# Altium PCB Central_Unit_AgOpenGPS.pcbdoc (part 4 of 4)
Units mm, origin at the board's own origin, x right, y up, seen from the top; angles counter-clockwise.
Board outline 200.19 x 122.57 mm, 2 copper layers (Top Layer, Bottom Layer); 271 components, 213 nets, 1023 pads, 412 vias.
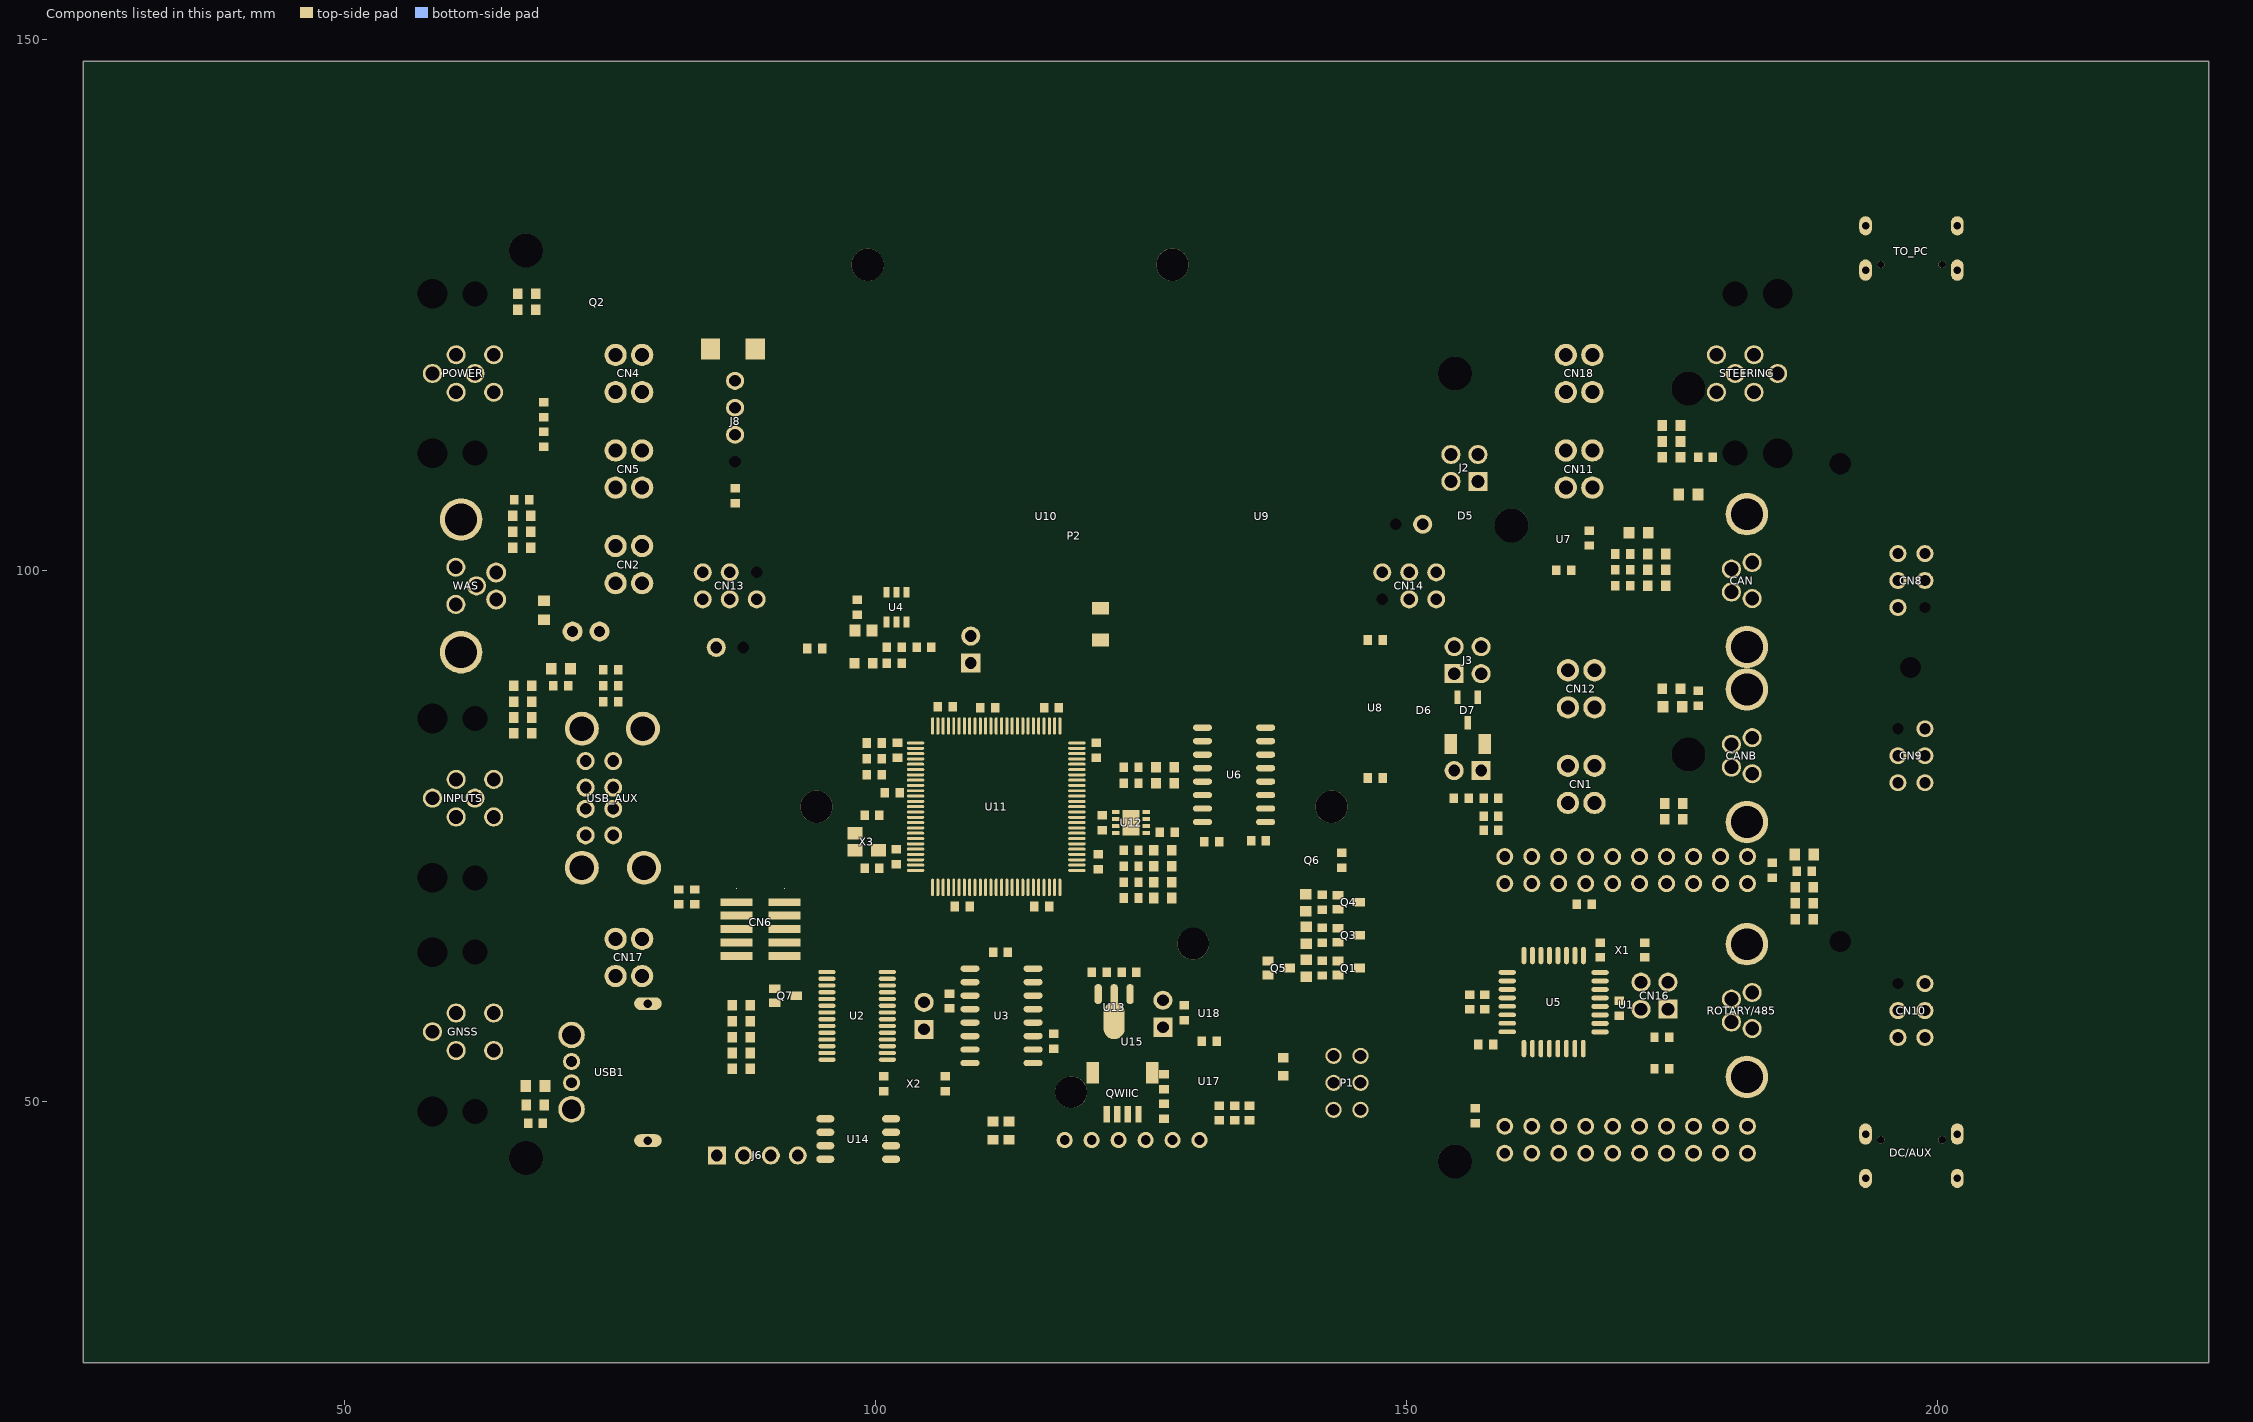
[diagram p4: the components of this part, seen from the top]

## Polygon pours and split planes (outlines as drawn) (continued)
GND2 on Top Layer (solid): 192.987,42.366 202.387,42.366 202.487,42.466 202.487,87.766 201.087,89.166 194.187,89.166 192.887,87.866
+3V3 on Top Layer (solid): 104.187,75.366 104.187,83.866 105.387,85.066 105.287,85.066 105.387,85.066 117.387,85.066 118.687,83.766 118.687,71.766 117.387,70.466 107.987,70.666 105.137,73.516 104.487,73.666 104.187,74.866
GND on Top Layer (solid): 53.888,132.116 54.838,133.066 56.088,133.066 108.638,133.066 118.837,133.066 143.887,133.066 169.037,133.066 179.687,133.066 189.137,133.066 189.137,42.616 188.587,42.066 54.688,42.066 53.788,42.966

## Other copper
Top Layer:
  region: 191.387,65.566 191.387,64.566 190.387,64.566 190.387,65.566
  region: 196.987,91.366 197.987,91.366 197.987,90.366 196.987,90.366
  region: 191.387,110.566 191.387,109.566 190.387,109.566 190.387,110.566
  rectangle net MB: 167.787,120.066 178.787,122.416
  rectangle net +5V: 115.837,44.416 116.437,44.666
  rectangle net +MOTOR: 99.587,122.116 102.787,125.816
  rectangle net MA: 105.087,116.966 126.237,130.816
  rectangle net STEERENABLE: 136.487,63.566 136.987,64.266
  rectangle net +3V3: 130.637,58.166 131.687,58.566
  rectangle net +5V: 94.987,89.966 98.487,91.166
  rectangle net +5V: 95.287,90.766 97.487,91.566
  rectangle net +5V: 95.587,91.566 96.087,92.566
  rectangle net +5V: 94.687,90.866 95.787,93.766
  rectangle net +VIN: 96.087,96.866 98.187,98.066
  rectangle net +3V3: 135.187,57.566 135.887,58.666
  rectangle net MB: 135.928,101.063 136.822,106.039
  rectangle net VBUS1: 199.687,125.966 200.287,127.166
  rectangle net VBUS1: 194.887,125.966 195.487,127.166
  rectangle net DP2: 197.187,48.166 197.387,48.966
  rectangle net VBUS2: 199.687,47.166 200.287,48.966
  rectangle net VBUS2: 194.887,46.966 195.487,48.766
  rectangle net MB: 130.887,105.766 152.387,122.366
  rectangle net GND: 98.987,95.866 104.287,97.266
  rectangle net +VIN: 97.787,97.466 101.287,98.166
  rectangle net +VIN: 96.487,97.966 101.287,99.666
  rectangle net +SMPS: 96.087,100.266 98.087,103.666
  rectangle net -MOTOR: 86.787,123.866 90.587,126.266
  rectangle net +MOTOR: 119.487,97.366 126.087,101.466
  rectangle net -MOTOR: 126.787,95.866 132.687,101.516
  rectangle net MB: 130.887,121.966 179.537,130.966
  rectangle net MA: 110.887,105.566 130.687,126.866
  rectangle net -MOTOR: 126.787,100.766 132.987,105.266
  rectangle net -MOTOR: 111.787,102.166 127.087,105.266
  rectangle net -MOTOR: 111.887,101.366 112.687,102.366
  rectangle net GND: 120.887,55.466 124.137,58.916
  rectangle net GND: 121.587,58.616 123.387,63.266
  region net +MOTOR: 140.197,99.782 140.703,99.782 142.087,101.166 143.187,102.266 143.187,103.966 140.287,103.966 139.787,103.466 139.787,100.192 140.197,99.782
Bottom Layer:
  region: 191.387,65.566 191.387,64.566 190.387,64.566 190.387,65.566
  region: 196.987,91.366 197.987,91.366 197.987,90.366 196.987,90.366
  region: 191.387,110.566 191.387,109.566 190.387,109.566 190.387,110.566
  rectangle net -MOTOR: 65.387,114.666 74.087,118.766
  rectangle net -MOTOR: 63.487,118.266 75.987,121.666
  rectangle net VBUS1: 195.487,103.766 199.387,106.266
  rectangle net VBUS2: 195.587,51.066 199.487,53.566
  rectangle net MA: 186.087,117.816 189.188,122.006
  rectangle net +MOTOR: 53.587,113.416 62.237,117.416

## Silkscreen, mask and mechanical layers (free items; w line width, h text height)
Top Overlay:
  lines w0.15 net S$18375: 53.287,43.563 189.287,43.566 ; 53.287,131.566 189.387,131.566
  lines w0.15 net S$55412: 94.587,128.666 96.987,131.066 97.687,131.066 129.887,131.066 132.387,128.566 143.787,128.566 145.287,127.066
  lines w0.15 net S$55414: 91.887,126.966 91.887,127.666 92.887,128.666 94.587,128.666
  lines w0.15 net S$55416: 145.287,120.166 145.287,93.066 ; 145.287,93.066 145.287,93.066
  lines w0.15 net S$55418: 145.287,89.066 145.287,90.766
  lines w0.15 net S$55420: 145.287,77.866 145.287,84.966
  lines w0.15 net S$55422: 145.287,70.066 145.287,70.966
  lines w0.15 net S$55424: 145.287,66.966 145.287,67.566
  lines w0.15 net S$55426: 145.287,63.766 145.287,64.466
  lines w0.15 net S$55428: 142.987,62.466 143.887,62.466
  lines w0.15 net S$55430: 133.687,62.466 139.487,62.466
  lines w0.15 net S$55432: 128.787,62.466 133.087,62.466
  lines w0.15 net S$55434: 118.087,62.566 119.287,62.566
  lines w0.15 net S$55436: 114.087,62.466 115.687,62.466
  lines w0.15 net S$55438: 107.987,62.466 109.687,62.466
  lines w0.15 net S$55440: 100.487,62.466 102.787,62.466
  lines w0.15 net S$55442: 94.687,62.466 96.187,62.466
  lines w0.15 net S$55444: 91.987,81.566 91.987,63.166 92.287,62.866
  lines w0.15 net S$55446: 91.987,87.166 91.987,92.866
  lines w0.15 net S$55452: 177.087,76.666 179.087,76.666
  lines w0.15 net S$55454: 179.087,76.716 179.087,83.066
  lines w0.15 net S$55456: 179.087,91.566 179.087,106.266
  lines w0.15 net S$55458: 179.087,114.566 179.087,122.766
  lines w0.15 net S$55460: 149.487,126.666 177.487,126.666
  lines w0.15 net S$55462: 147.987,76.666 152.787,76.666
  lines w0.15 net S$55464: 129.087,105.266 129.087,114.366
  lines w0.15 net S$55466: 129.087,96.666 129.087,103.366
  lines w0.15 net S$55468: 129.087,85.866 129.087,88.966
  lines w0.15 net S$55470: 129.787,76.666 131.587,76.666
  lines w0.15 net S$55472: 129.087,77.966 129.087,82.466
  lines w0.15 net S$55474: 135.987,76.666 141.387,76.666
  text "Ardusimple" at 132.678,128.566 h1 r359
  text "QtOpenGuidance" at 120.287,117.45 h2.03
  text "V1.1" at 128.237,114.2 h2.03
  text "CANtact" at 105.587,74.25 h2.03
  text "o" at 91.435,70.026 h1 r136
Top Solder:
  region: 191.387,65.566 191.387,64.566 190.387,64.566 190.387,65.566
  region: 196.987,91.366 197.987,91.366 197.987,90.366 196.987,90.366
  region: 191.387,110.566 191.387,109.566 190.387,109.566 190.387,110.566
  text "12-2020" at 122.687,110.066 h2.03
Bottom Solder:
  region: 191.387,65.566 191.387,64.566 190.387,64.566 190.387,65.566
  region: 196.987,91.366 197.987,91.366 197.987,90.366 196.987,90.366
  region: 191.387,110.566 191.387,109.566 190.387,109.566 190.387,110.566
